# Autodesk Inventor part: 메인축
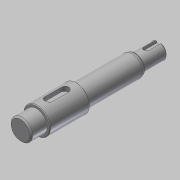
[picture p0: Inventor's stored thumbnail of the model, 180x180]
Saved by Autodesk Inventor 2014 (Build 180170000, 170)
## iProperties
Created: 2019-03
Part Number: 메인축
Material: 강철, 연강
Document SubType Name: Modeling
Designer: mduedu
Density: 1 g/cm^3
Appearance: 강철
Author: mduedu
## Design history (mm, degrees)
sketch "스케치1"
  geometry: L1 (0, 0)-(12, 0); L2 (12, 0)-(12, 8); L3 (12, 8)-(0, 8); L4 (0, 8)-(0, 0); L5 (12, 0)-(42, 0); L6 (42, 0)-(42, 10); L7 (42, 10)-(12, 10); L8 (12, 10)-(12, 0); L9 (42, 0)-(86, 0); L10 (86, 0)-(86, 8); L11 (86, 8)-(42, 8); L12 (42, 8)-(42, 0); L13 (86, 0)-(104, 0); L14 (104, 0)-(104, 6); L15 (104, 6)-(86, 6); L16 (86, 6)-(86, 0)
  constraints: 32 end point, 8 parallel, 4 horizontal, 4 perpendicular
  dimensions: "d0" = 16 diameter of L3 L1; "d2" = 20 diameter of L7 L5; "d3" = 16 diameter of L11 L9; "d4" = 12 diameter of L15 L13; "d5" = 12 distance of L2.end L3.end; "d6" = 30 distance of L6.end L7.end; "d7" = 86 distance between parallel lines of L10 L4; "d8" = 104 distance between parallel lines of L14 L4
revolve "회전1" sketch "스케치1" stored, may be unused: angle "d9" = 90 deg
node "작업 평면1"
sketch "스케치2" dims "d10" = 18
  geometry: L1 (6, -3)-(-6, -3); L2 (-6, -3)-(-6, 3); L3 (-6, 3)-(6, 3); L4 (6, 3)-(6, -3); L5 (15, 10)-(15, -10) reference; 3 further points
  constraints: 8 end point, 2 midpoint, 2 parallel, 2 vertical alignment, 1 horizontal, 1 horizontal alignment, 1 perpendicular, 4 other
  dimensions: "d12" = 6 distance between parallel lines of L3 L1; "d13" = 6 dimension on L5
extrude "돌출1" cut sketch "스케치2" distance "d14" = 3.5; taper "d15" = 0 deg
node "작업 평면2"
sketch "스케치3"
  geometry: L1 (-9, 6)-(-9, -6) reference; L2 (1, -2)-(-9, -2); L3 (1, 2)-(-9, 2); A1 r 2 centre (1, 0) between (1, -2) and (1, 2); 2 further points
  constraints: 4 end point, 2 point on circle, 2 point on line, 2 tangent, 1 centre point, 1 horizontal alignment, 1 midpoint, 1 parallel, 1 perpendicular
  dimensions: "d16" = 12 dimension on A1 L1; "d17" = 4 distance between parallel lines of L3 L2
extrude "돌출2" cut sketch "스케치3" distance "d18" = 2.5; taper "d19" = 0 deg
chamfer "모따기1" distance "d20" = 1; stored, may be unused: second distance "d21" = 2, angle "d22" = 45 deg
chamfer "모따기2" distance "d23" = 0.5; stored, may be unused: second distance "d24" = 2, angle "d25" = 45 deg
chamfer "모따기3" distance "d26" = 1.73; stored, may be unused: second distance "d27" = 2, angle "d28" = 30 deg
fillet "모깎기2" dims "d31" = 0.5, "d32" = 4
node "솔리드1"
